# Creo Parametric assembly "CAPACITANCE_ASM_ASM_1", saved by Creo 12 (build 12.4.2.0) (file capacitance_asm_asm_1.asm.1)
Units: Custom; MM, KILOGRAM, SECS

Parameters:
  PTC_WM_ITERATION = "0"
  PTC_WM_VERSION = "-.0"
  PTC_WM_LIFECYCLE_STATE = "In Work"
  PTC_WM_LIFECYCLE = "MO_CADDocument"
  PTC_WM_CREATED_BY = "Maximilian Roepper (Z0017RMS: MO)"
  PTC_WM_CREATED_ON = "18-Sep-26 11:36:42 AM"
  PTC_WM_MODIFIED_BY = "Maximilian Roepper (Z0017RMS: MO)"
  PTC_WM_MODIFIED_ON = "18-Sep-26 11:36:46 AM"
  PDMLINKNUMBER = "PDM000071455001"
  PTC_WM_NUMBER = "PDM000071455001"

Other parameters: WEIGHT, WEIGHT_FACTOR, WEIGHT_ADD, MC_ERRORS, SUPPLIER

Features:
  1. coordinate system
  2. imported feature
  3. component "C_0603__PRT_1"
  4. component "C_0603_001_PRT_1"
  5. component "C_0603_002_PRT_1"
  6. component "C_0603_003_PRT_1"
  7. component "C_0603_004_PRT_1"
  8. component "C_0603_005_PRT_1"
  9. component "C_1206_001_PRT_1"
  10. component "C_1206_002_PRT_1"

Other named items: DRW_VIEW_ORG, ROUGH-GROB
